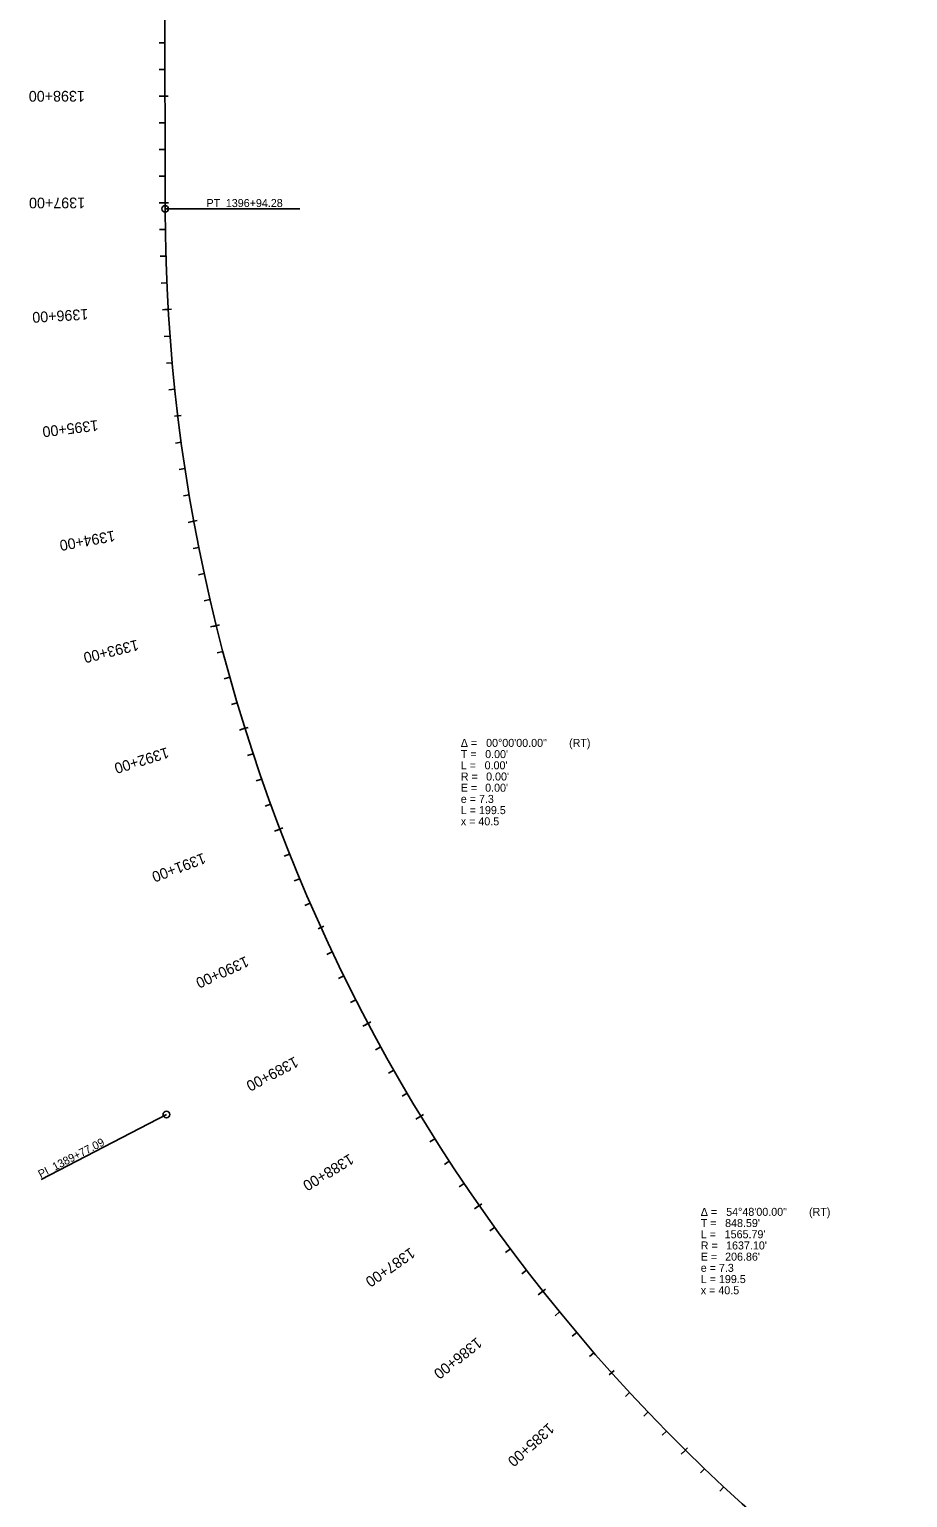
# Model space of a CAD drawing. Extents: x 14541681 to 14544384, y 8572153 to 8583558.
# Drawn here: x 14541684 to 14542507, y 8579336 to 8580711 of the extents above; entities that cross this region are included whole.
import ezdxf

# ---------------------------------------------------------------- set-up
doc = ezdxf.new("R2010")
doc.units = 0
for name, color, linetype in [('Alignment', 7, 'Continuous'), ('TextAlignment', 7, 'Continuous'), ('TextAlignmentLrg', 7, 'Continuous'), ('TextAlignmentSml', 7, 'Continuous')]:
    doc.layers.add(name, color=color, linetype=linetype)

msp = doc.modelspace()

# ---------------------------------------------------------------- linework, layer by layer
at = {"layer": 'Alignment'}
msp.add_line((14541811.5, 8580543.1), (14541807.4, 8583548.8), dxfattribs=at)
msp.add_arc((14543448.6, 8580545.3), 1637.1, 180.077, 234.877, dxfattribs=at)
at = {"layer": 'TextAlignment'}
for p, q in [((14541811.5, 8580543.1), (14541937.5, 8580543.3)), ((14541937.5, 8580543.3), (14541937.5, 8580543.3)), ((14541812.6, 8579694.5), (14541695.5, 8579633.6)), ((14541695.5, 8579633.6), (14541695.5, 8579633.6))]:
    msp.add_line(p, q, dxfattribs=at)
for centre in [(14541811.5, 8580543.1), (14541812.6, 8579694.5)]:
    msp.add_circle(centre, 3.12, dxfattribs=at)
at = {"layer": 'TextAlignmentLrg'}
for p, q in [((14541811.3, 8580648.8), (14541805.9, 8580648.8)), ((14541811.5, 8580548.8), (14541806, 8580548.8)), ((14541814.3, 8580448.9), (14541808.9, 8580448.5)), ((14541820.2, 8580348.9), (14541826.3, 8580349.6)), ((14541838.3, 8580250.4), (14541832.9, 8580249.4)), ((14541859.3, 8580152.7), (14541854, 8580151.4)), ((14541886.2, 8580056.4), (14541881, 8580054.8)), ((14541918.9, 8579961.9), (14541913.8, 8579960)), ((14541954.6, 8579868.4), (14541960.2, 8579870.9)), ((14542001.4, 8579779.9), (14541996.6, 8579777.3)), ((14542050.9, 8579692.9), (14542046.2, 8579690.1)), ((14542105.5, 8579609.2), (14542101, 8579606.1)), ((14542165.2, 8579529), (14542160.9, 8579525.6)), ((14542227.3, 8579450.5), (14542231.9, 8579454.6)), ((14542298.6, 8579380.1), (14542294.7, 8579376.3))]:
    msp.add_line(p, q, dxfattribs=at)
at = {"layer": 'TextAlignmentSml'}
for p, q in [((14541811.3, 8580698.8), (14541805.8, 8580698.8)), ((14541811.3, 8580673.8), (14541805.8, 8580673.8)), ((14541808.3, 8580648.8), (14541814.4, 8580648.8)), ((14541811.4, 8580623.8), (14541805.9, 8580623.8)), ((14541811.4, 8580598.8), (14541805.9, 8580598.8)), ((14541811.4, 8580573.8), (14541806, 8580573.8)), ((14541808.4, 8580548.8), (14541814.5, 8580548.8)), ((14541811.6, 8580523.8), (14541806.2, 8580523.7)), ((14541812.1, 8580498.8), (14541806.7, 8580498.7)), ((14541813, 8580473.8), (14541807.6, 8580473.6)), ((14541811.3, 8580448.7), (14541817.4, 8580449)), ((14541816, 8580423.9), (14541810.5, 8580423.5)), ((14541818, 8580399), (14541812.6, 8580398.5)), ((14541820.5, 8580374.1), (14541815, 8580373.6)), ((14541820.2, 8580348.9), (14541826.3, 8580349.6)), ((14541826.4, 8580324.5), (14541821, 8580323.7)), ((14541830, 8580299.7), (14541824.6, 8580298.9)), ((14541833.9, 8580275.1), (14541828.6, 8580274.2)), ((14541835.2, 8580249.9), (14541841.3, 8580251)), ((14541842.9, 8580225.9), (14541837.6, 8580224.8)), ((14541848, 8580201.4), (14541842.7, 8580200.2)), ((14541853.4, 8580177), (14541848.1, 8580175.8)), ((14541856.3, 8580151.9), (14541862.2, 8580153.4)), ((14541865.4, 8580128.5), (14541860.2, 8580127.1)), ((14541872, 8580104.3), (14541866.7, 8580102.9)), ((14541878.9, 8580080.3), (14541873.7, 8580078.8)), ((14541883.3, 8580055.5), (14541889.1, 8580057.3)), ((14541893.8, 8580032.6), (14541888.7, 8580030.9)), ((14541901.8, 8580008.9), (14541896.7, 8580007.1)), ((14541910.2, 8579985.3), (14541905.1, 8579983.5)), ((14541916.1, 8579960.8), (14541921.8, 8579963)), ((14541928, 8579938.6), (14541923, 8579936.6)), ((14541937.5, 8579915.5), (14541932.4, 8579913.4)), ((14541947.3, 8579892.5), (14541942.3, 8579890.3)), ((14541954.6, 8579868.4), (14541960.2, 8579870.9)), ((14541967.9, 8579846.9), (14541963, 8579844.6)), ((14541978.7, 8579824.4), (14541973.8, 8579822)), ((14541989.9, 8579802), (14541985.1, 8579799.6)), ((14541998.7, 8579778.4), (14542004.1, 8579781.3)), ((14542013.3, 8579757.9), (14542008.5, 8579755.2)), ((14542025.5, 8579736), (14542020.7, 8579733.3)), ((14542038, 8579714.4), (14542033.3, 8579711.6)), ((14542048.3, 8579691.4), (14542053.5, 8579694.5)), ((14542064, 8579671.7), (14542059.4, 8579668.8)), ((14542077.5, 8579650.7), (14542073, 8579647.7)), ((14542091.4, 8579629.8), (14542086.8, 8579626.8)), ((14542103, 8579607.5), (14542108, 8579611)), ((14542120, 8579588.8), (14542115.5, 8579585.6)), ((14542134.7, 8579568.6), (14542130.3, 8579565.4)), ((14542149.8, 8579548.7), (14542145.5, 8579545.4)), ((14542162.8, 8579527.1), (14542167.6, 8579530.9)), ((14542180.8, 8579509.5), (14542176.6, 8579506)), ((14542196.8, 8579490.3), (14542192.6, 8579486.7)), ((14542213, 8579471.3), (14542208.9, 8579467.7)), ((14542227.3, 8579450.5), (14542231.9, 8579454.6)), ((14542246.4, 8579434), (14542242.4, 8579430.3)), ((14542263.5, 8579415.8), (14542259.6, 8579412)), ((14542280.9, 8579397.8), (14542277, 8579394)), ((14542296.4, 8579378), (14542300.7, 8579382.3)), ((14542316.5, 8579362.7), (14542312.7, 8579358.8)), ((14542334.7, 8579345.6), (14542331, 8579341.6))]:
    msp.add_line(p, q, dxfattribs=at)

# ---------------------------------------------------------------- texts
at = {"layer": 'TextAlignment'}
for s, rotation, p in [('PT', 0.077, (14541850.2, 8580544.8)), ('1396+94.28', 0.077, (14541868.3, 8580544.8)), ('1389+77.09', 27.477, (14541708.2, 8579641.7)), ('PI ', 27.477, (14541694.9, 8579634.8))]:
    msp.add_text(s, height=7.5, rotation=rotation, dxfattribs=at).set_placement(p)
for s, p in [('T = ', (14542088.3, 8580028.5)), ('Δ = ', (14542088.3, 8580039)), ("0.00'", (14542111.1, 8580028.5)), ('00°00\'00.00"', (14542112, 8580039)), (' (RT)', (14542186.9, 8580039)), ('L = ', (14542088.3, 8580018)), ("0.00'", (14542110.6, 8580018)), ('R = ', (14542088.3, 8580007.5)), ("0.00'", (14542112, 8580007.5)), ('e = 7.3', (14542088.3, 8579986.5)), ('E = ', (14542088.3, 8579997)), ("0.00'", (14542111.1, 8579997)), ('L = 199.5', (14542088.3, 8579976)), ('x = 40.5', (14542088.3, 8579965.5)), ('T = ', (14542313, 8579589.1)), ('Δ = ', (14542313, 8579599.6)), ("848.59'", (14542335.8, 8579589.1)), ('54°48\'00.00"', (14542336.8, 8579599.6)), (' (RT)', (14542411.6, 8579599.6)), ('L = ', (14542313, 8579578.6)), ("1565.79'", (14542335.4, 8579578.6)), ('R = ', (14542313, 8579568.1)), ("1637.10'", (14542336.7, 8579568.1)), ('e = 7.3', (14542313, 8579547.1)), ('E = ', (14542313, 8579557.6)), ("206.86'", (14542335.8, 8579557.6)), ('L = 199.5', (14542313, 8579536.6)), ('x = 40.5', (14542313, 8579526.1))]:
    msp.add_text(s, height=7.5, dxfattribs=at).set_placement(p)
at = {"layer": 'TextAlignmentLrg'}
for s, rotation, p in [('1395+00', 186.8767, (14541748.2, 8580345.3)), ('1390+00', 204.3759, (14541887, 8579843.2)), ('1385+00', 221.875, (14542170.4, 8579406.2))]:
    msp.add_text(s, height=10.02, rotation=rotation, dxfattribs=at).set_placement(p)
at = {"layer": 'TextAlignmentSml'}
for s, rotation, p in [('1398+00', 180.077, (14541736.3, 8580653.7)), ('1397+00', 180.077, (14541736.5, 8580553.7)), ('1396+00', 183.3769, (14541739.2, 8580449.4)), ('1395+00', 186.8767, (14541748.2, 8580345.3)), ('1394+00', 190.3765, (14541763.6, 8580241.8)), ('1393+00', 193.8764, (14541785.2, 8580139.6)), ('1392+00', 197.3762, (14541813.1, 8580038.8)), ('1391+00', 200.876, (14541847.1, 8579939.9)), ('1390+00', 204.3759, (14541887, 8579843.2)), ('1389+00', 207.8757, (14541932.8, 8579749.2)), ('1388+00', 211.3755, (14541984.2, 8579658.2)), ('1387+00', 214.8754, (14542041.1, 8579570.4)), ('1386+00', 218.3752, (14542103.2, 8579486.3)), ('1385+00', 221.875, (14542170.4, 8579406.2))]:
    msp.add_text(s, height=10.02, rotation=rotation, dxfattribs=at).set_placement(p)

doc.saveas('drawing.dxf')
